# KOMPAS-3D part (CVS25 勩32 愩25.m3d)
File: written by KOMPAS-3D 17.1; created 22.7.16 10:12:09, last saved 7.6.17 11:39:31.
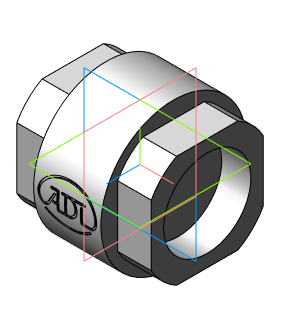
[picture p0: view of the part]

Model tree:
1. Операция без истории:2  (labels: Сталь 20  ГОСТ 1050-88)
